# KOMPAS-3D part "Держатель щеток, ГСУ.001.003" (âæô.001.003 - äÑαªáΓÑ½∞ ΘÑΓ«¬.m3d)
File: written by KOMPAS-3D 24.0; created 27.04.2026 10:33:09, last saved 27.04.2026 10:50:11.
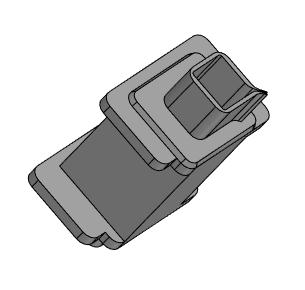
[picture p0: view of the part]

Document properties: Автор: User7; Полное имя файла: C:\Users\User7\Desktop\олимп\ГСУ.001.003 - Держатель щеток.m3d

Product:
- Part/product: Держатель щеток  | designation ГСУ.001.003
    Масса: 0.006051

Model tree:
1. Эскиз:1
2. Элемент выдавливания:1
     Расстояние 1 = 20
3. Скругление:1  (with: Ребро.Элемент выдавливания:1)
     Радиус = 1
4. Скругление:2  (with: Ребро.Элемент выдавливания:1)
     Радиус = 0.2
5. Скругление:3  (with: Ребро.Элемент выдавливания:1)
     Радиус = 1
6. Эскиз:2  (with: Ребро.Элемент выдавливания:1, Вершина.Скругление:3, Ребро.Скругление:3, Вершина.Скругление:1, Ребро.Скругление:1, Ребро.Скругление:2)
7. Элемент выдавливания:2
     Расстояние 1 = 6.5; Расстояние 2 = 5.5
8. Эскиз:3  (with: Грань.Элемент выдавливания:2, Ребро.Элемент выдавливания:2)
9. Элемент выдавливания:3
     Расстояние 2 = 1
10. Скругление:4  (with: Ребро.Элемент выдавливания:3)
     Радиус = 1
11. Эскиз:4  (with: Грань.Элемент выдавливания:2, Ребро.Элемент выдавливания:3, Ребро.Скругление:4)
12. Элемент выдавливания:4
     Расстояние 2 = 1
13. Эскиз:5  (with: Грань.Элемент выдавливания:2, Ребро.Элемент выдавливания:2, Ребро.Элемент выдавливания:4)
14. Элемент выдавливания:5
     Расстояние 1 = 0.5
15. Фаска:1  (with: Ребро.Элемент выдавливания:5)
     Угол = 25; Длина 1 = 0.5; Длина 2 = 0.233154

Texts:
  ГСУ.001.003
